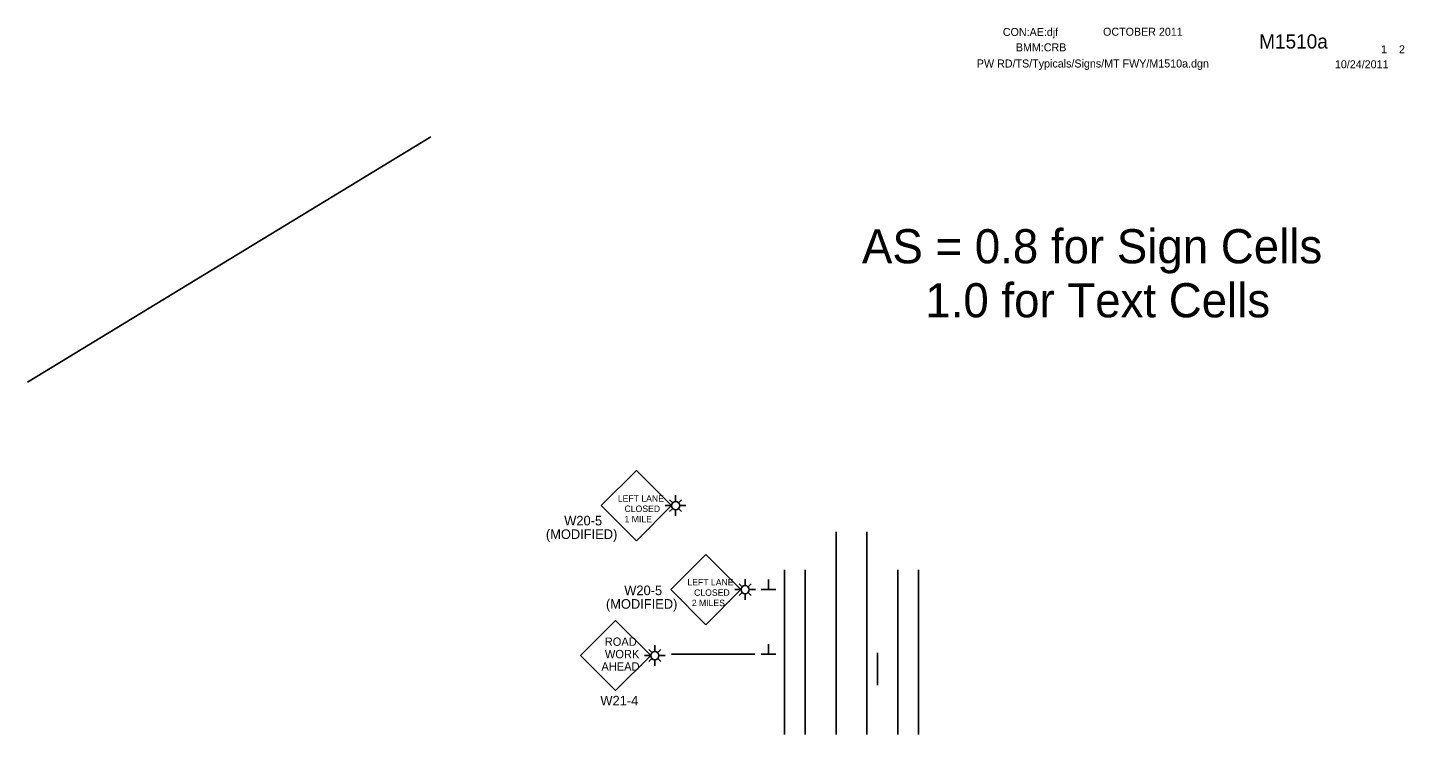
# Model space of a CAD drawing. Extents: x 16335 to 18464, y 5417 to 6974.
# Drawn here: x 16335 to 17402, y 5417 to 5965 of the extents above; entities that cross this region are included whole.
import ezdxf

# ---------------------------------------------------------------- set-up
doc = ezdxf.new("R2010")
doc.units = 0
for name, color, linetype in [('ALI_LEGAL_EX', 7, 'Continuous'), ('BORDER_SIGNAL_WO', 7, 'Continuous'), ('PAVT_EDGE_EX', 7, 'Continuous'), ('TRAFFIC_SIGNS_PR', 7, 'Continuous'), ('TYPICAL_TEXT_DIMEN_PR', 7, 'Continuous')]:
    doc.layers.add(name, color=color, linetype=linetype)

msp = doc.modelspace()

# ---------------------------------------------------------------- linework, layer by layer
at = {"layer": 'ALI_LEGAL_EX'}
for p, q in [((16961.5, 5574.3), (16961.5, 5417.4)), ((16985.5, 5574.3), (16985.5, 5417.4))]:
    msp.add_line(p, q, dxfattribs=at)
for points in [[(16961.5, 5544.9), (16961.5, 5519.9)], [(16985.5, 5544.9), (16985.5, 5519.9)], [(16993.6, 5480.5), (16993.6, 5455.5)], [(16961.5, 5444.9), (16961.5, 5419.9)], [(16985.5, 5444.9), (16985.5, 5419.9)]]:
    msp.add_lwpolyline(points, dxfattribs=at)
at = {"layer": 'PAVT_EDGE_EX'}
for p, q in [((16921.5, 5544.9), (16921.5, 5417.4)), ((16937.5, 5544.9), (16937.5, 5417.4)), ((17009.5, 5544.9), (17009.5, 5417.4)), ((17025.5, 5544.9), (17025.5, 5417.4))]:
    msp.add_line(p, q, dxfattribs=at)
at = {"layer": 'TRAFFIC_SIGNS_PR'}
for p, q in [((16806.9, 5621.7), (16779.7, 5594.5)), ((16834.1, 5594.5), (16806.9, 5621.7)), ((16834.8, 5597), (16832.6, 5599.1)), ((16837.3, 5598), (16837.3, 5602.5)), ((16839.8, 5597), (16841.9, 5599.1)), ((16779.7, 5594.5), (16806.9, 5567.3)), ((16806.9, 5567.3), (16834.1, 5594.5)), ((16834.1, 5594.5), (16829.2, 5594.5)), ((16834.8, 5592), (16832.6, 5589.9)), ((16837.3, 5586.5), (16837.3, 5590.9)), ((16839.8, 5592), (16841.9, 5589.9)), ((16840.4, 5594.5), (16845.3, 5594.5)), ((16860.8, 5556.7), (16833.6, 5529.5)), ((16887.9, 5529.5), (16860.8, 5556.7)), ((16891.1, 5533.1), (16891.1, 5537.6)), ((16833.6, 5529.5), (16860.8, 5502.3)), ((16860.8, 5502.3), (16887.9, 5529.5)), ((16887.9, 5529.5), (16883.1, 5529.5)), ((16888.6, 5532), (16886.5, 5534.1)), ((16888.6, 5527), (16886.5, 5524.9)), ((16891.1, 5521.6), (16891.1, 5526)), ((16893.6, 5532), (16895.7, 5534.1)), ((16893.6, 5527), (16895.7, 5524.9)), ((16894.2, 5529.5), (16899.1, 5529.5)), ((16790.8, 5505.6), (16763.7, 5478.4)), ((16818, 5478.4), (16790.8, 5505.6)), ((16818.7, 5481), (16816.6, 5483.1)), ((16821.2, 5482), (16821.2, 5486.5)), ((16823.7, 5481), (16825.8, 5483.1)), ((16763.7, 5478.4), (16790.8, 5451.3)), ((16790.8, 5451.3), (16818, 5478.4)), ((16818, 5478.4), (16813.1, 5478.4)), ((16818.7, 5475.9), (16816.6, 5473.8)), ((16821.2, 5470.5), (16821.2, 5474.9)), ((16823.7, 5475.9), (16825.8, 5473.8)), ((16824.3, 5478.4), (16829.2, 5478.4))]:
    msp.add_line(p, q, dxfattribs=at)
for centre in [(16837.3, 5594.5), (16891.1, 5529.5), (16821.2, 5478.4)]:
    msp.add_circle(centre, 3.15, dxfattribs=at)
at = {"layer": 'TYPICAL_TEXT_DIMEN_PR'}
for p, q in [((16647.8, 5880), (16335.3, 5690.2)), ((16909.1, 5529.5), (16909.1, 5537.3)), ((16903.5, 5529.5), (16914.8, 5529.5)), ((16909.1, 5479.5), (16909.1, 5487.3)), ((16834.1, 5479.5), (16898.5, 5479.5)), ((16903.5, 5479.5), (16914.8, 5479.5))]:
    msp.add_line(p, q, dxfattribs=at)

# ---------------------------------------------------------------- texts
at = {"layer": 'BORDER_SIGNAL_WO'}
for s, height, p in [('CON:AE:djf  ', 6.2, (17090.7, 5958.1)), ('    OCTOBER 2011    ', 6.2, (17159.1, 5958.3)), ('BMM:CRB   ', 6.2, (17100.8, 5946.2)), ('    M1510a   ', 11, (17272.9, 5948.4)), (' 1    2 ', 6.2, (17381.4, 5944.7)), ('PW RD/TS/Typicals/Signs/MT FWY/M1510a.dgn      ', 6.2, (17070.6, 5933.7)), ('10/24/2011    ', 6.2, (17347.9, 5933.1)), ('AS = 0.8 for Sign Cells', 26.424, (16981.6, 5782.1)), ('     1.0 for Text Cells', 26.424, (16981.6, 5740.3))]:
    msp.add_text(s, height=height, dxfattribs=at).set_placement(p)
at = {"layer": 'TRAFFIC_SIGNS_PR'}
for s, height, p in [('LEFT LANE', 5.01, (16792.5, 5597.6)), ('CLOSED', 5.01, (16797.7, 5589.6)), ('W20-5', 7.45, (16751, 5579.2)), ('1 MILE', 5.01, (16797.7, 5581.6)), ('(MODIFIED)', 7.45, (16736.8, 5568.7)), ('LEFT LANE', 5.01, (16846.4, 5532.7)), ('W20-5', 7.45, (16797.5, 5525.2)), ('CLOSED', 5.01, (16851.6, 5524.7)), ('(MODIFIED)', 7.45, (16783.3, 5514.7)), ('2 MILES', 5.01, (16849.8, 5516.7)), ('ROAD', 6.41, (16782.4, 5486)), ('WORK', 6.41, (16782.5, 5476.4)), ('AHEAD', 6.41, (16779.8, 5466.8)), ('W21-4', 7.45, (16779, 5439.8))]:
    msp.add_text(s, height=height, dxfattribs=at).set_placement(p)

doc.saveas('drawing.dxf')
